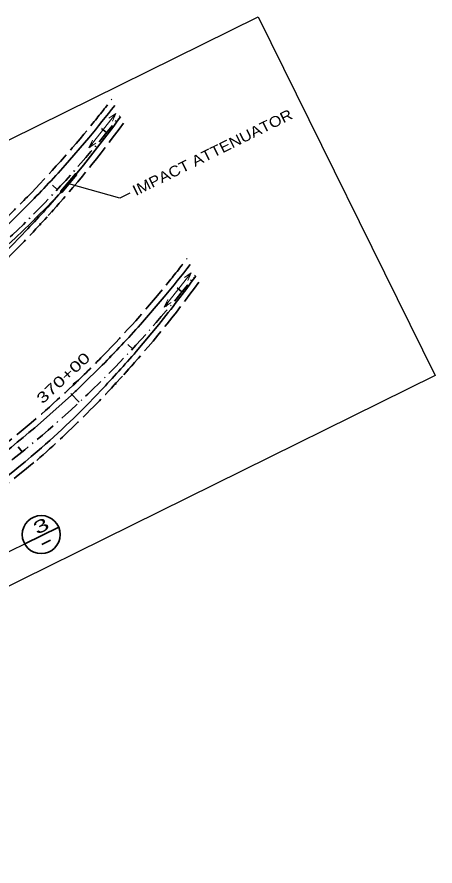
# Model space of a CAD drawing. Extents: x 2356431 to 2371438, y 6972864 to 6982525.
# Drawn here: x 2362282 to 2362836, y 6978847 to 6979972 of the extents above; entities that cross this region are included whole.
import ezdxf
from ezdxf.enums import TextEntityAlignment as Align

# ---------------------------------------------------------------- set-up
doc = ezdxf.new("R2010")
doc.units = 0
doc.header["$LTSCALE"] = 5.6
doc.linetypes.add('DOT_DASHED', pattern=[7.7, 5, -1.2, 0.3, -1.2])
doc.linetypes.add('LONG_DASHED', pattern=[7.5, 6, -1.5])
for name, color, linetype, lineweight in [('14', 7, 'Continuous', 13), ('17', 7, 'Continuous', 35), ('2', 7, 'Continuous', 35), ('24', 7, 'Continuous', 13), ('28', 7, 'Continuous', 35), ('6', 7, 'DOT_DASHED', 35), ('8', 7, 'Continuous', 13)]:
    doc.layers.add(name, color=color, linetype=linetype, lineweight=lineweight)

msp = doc.modelspace()

# ---------------------------------------------------------------- linework, layer by layer
at = {"layer": '14'}
for p, q in [((2362413.315, 6979843.481), (2362404.062, 6979837.394)), ((2362413.315, 6979843.481), (2362408.657, 6979833.432)), ((2362377.511, 6979798.212), (2362382.219, 6979808.24)), ((2362513.151, 6979632.555), (2362503.898, 6979626.468)), ((2362513.151, 6979632.555), (2362508.493, 6979622.506)), ((2362477.347, 6979587.286), (2362482.055, 6979597.314))]:
    msp.add_line(p, q, dxfattribs=at)
for points in [[(2362413.315, 6979843.481), (2362377.511, 6979798.212), (2362386.795, 6979804.255)], [(2362513.151, 6979632.555), (2362477.347, 6979587.286), (2362486.631, 6979593.329)]]:
    msp.add_lwpolyline(points, dxfattribs=at)
at = {"layer": '17', "lineweight": 13}
for centre in [(2362381.177, 6979803.33), (2362312.936, 6979696.769), (2362481.013, 6979592.404), (2362412.772, 6979485.843)]:
    msp.add_circle(centre, 1, dxfattribs=at)
at = {"layer": '2'}
for p, q in [((2362377.323, 6979811.601), (2362345.907, 6979775.127)), ((2362340.219, 6979739.244), (2362370.285, 6979775.188)), ((2362295.276, 6979721.222), (2362267.688, 6979694.092)), ((2362477.159, 6979600.675), (2362445.743, 6979564.201)), ((2362440.055, 6979528.318), (2362470.121, 6979564.262)), ((2362395.112, 6979510.296), (2362367.524, 6979483.166)), ((2362354.349, 6979470.72), (2362313.384, 6979433.972)), ((2362292.462, 6979273.717), (2362337.516, 6979295.812)), ((2362315.084, 6979272.776), (2362326.522, 6979278.422))]:
    msp.add_line(p, q, dxfattribs=at)
at = {"layer": '2', "lineweight": 25}
msp.add_line((2361792.105, 6979026.773), (2362292.462, 6979273.717), dxfattribs=at)
msp.add_lwpolyline([(2361285.115, 6979321.851), (2362601.555, 6979971.558), (2362836.023, 6979496.478), (2361519.583, 6978846.77)], close=True, dxfattribs=at)
at = {"layer": '2'}
msp.add_lwpolyline([(2362339.613, 6979738.775), (2362340.156, 6979740.907), (2362359.585, 6979763.851), (2362361.205, 6979762.514), (2362341.898, 6979739.544)], close=True, dxfattribs=at)
at = {"layer": '2', "lineweight": 25}
msp.add_lwpolyline([(2362431.818, 6979738.252), (2362418.363, 6979731.611), (2362350.947, 6979750.54)], dxfattribs=at)
at = {"layer": '2'}
msp.add_circle((2362314.274, 6979285.825), 25.166, dxfattribs=at)
at = {"layer": '2', "linetype": 'LONG_DASHED'}
for centre, radius, start, end in [((2361287.072, 6980718.904), 1410.395, 320.86316, 322.61144), ((2361287.072, 6980718.904), 1410.395, 315.67541, 320.86316), ((2361256.679, 6980676.098), 1440.395, 317.79711, 324.08069), ((2361287.072, 6980718.904), 1410.395, 313.40549, 315.67541), ((2361256.679, 6980676.098), 1440.395, 311.35741, 318.66625), ((2361386.908, 6980507.978), 1410.395, 320.86316, 322.61144), ((2361386.908, 6980507.978), 1410.395, 315.67541, 320.86316), ((2361356.514, 6980465.172), 1440.395, 317.79711, 324.08069), ((2361356.514, 6980465.172), 1440.395, 311.35741, 318.66625), ((2361386.908, 6980507.978), 1410.395, 313.40549, 315.67541), ((2361386.908, 6980507.978), 1410.395, 304.27695, 313.40549), ((2361361.776, 6980498.253), 1461.395, 297.31887, 310.34554)]:
    msp.add_arc(centre, radius, start, end, dxfattribs=at)
at = {"layer": '2'}
for centre, radius, start, end in [((2361287.072, 6980718.904), 1418.395, 320.23288, 322.45152), ((2361256.679, 6980676.098), 1432.395, 321.02703, 324.24964), ((2361287.072, 6980718.904), 1418.395, 315.3005, 318.28822), ((2361256.679, 6980676.098), 1432.395, 316.36601, 319.15253), ((2361540.868, 6980387.624), 1027.726, 310.56789, 317.07313), ((2361386.908, 6980507.978), 1418.395, 320.23288, 322.45152), ((2361356.514, 6980465.172), 1432.395, 321.02703, 324.24964), ((2361386.908, 6980507.978), 1418.395, 315.3005, 318.28822), ((2361356.514, 6980465.172), 1432.395, 316.36601, 319.15253), ((2361386.908, 6980507.978), 1418.395, 313.00532, 313.73747), ((2361640.703, 6980176.698), 1027.726, 310.56789, 317.07313), ((2361386.908, 6980507.978), 1418.395, 304.27695, 310.78219), ((2361361.776, 6980498.253), 1453.395, 297.31887, 310.6767)]:
    msp.add_arc(centre, radius, start, end, dxfattribs=at)
at = {"layer": '24'}
for p, q in [((2362416.001, 6979835.063), (2362412.956, 6979832.475)), ((2362382.155, 6979801.83), (2362379.322, 6979799.003)), ((2362515.837, 6979624.137), (2362512.792, 6979621.549)), ((2362481.991, 6979590.904), (2362479.158, 6979588.077)), ((2362363.091, 6979490.308), (2362356.576, 6979485.655))]:
    msp.add_line(p, q, dxfattribs=at)
for points in [[(2362311.277, 6979737.172), (2362308.112, 6979734.552), (2362305.084, 6979732.103)], [(2362411.113, 6979526.246), (2362407.948, 6979523.626), (2362404.92, 6979521.177)]]:
    msp.add_lwpolyline(points, dxfattribs=at)
at = {"layer": '28'}
for p, q in [((2362400.953, 6979818.333), (2362394.344, 6979823.677)), ((2362335.419, 6979742.827), (2362329.198, 6979748.619)), ((2362500.789, 6979607.407), (2362494.18, 6979612.751)), ((2362435.255, 6979531.901), (2362429.034, 6979537.693)), ((2362364.614, 6979461.15), (2362353.693, 6979472.843)), ((2362289.209, 6979395.499), (2362283.855, 6979402.1))]:
    msp.add_line(p, q, dxfattribs=at)
at = {"layer": '6'}
for centre in [(2361287.074, 6980718.905), (2361386.91, 6980507.979)]:
    msp.add_arc(centre, 1432.395, 296.26348, 322.17641, dxfattribs=at)
at = {"layer": '6', "linetype": 'Continuous'}
msp.add_arc((2361291.383, 6980720.837), 1436.395, 298.99553, 316.8666, dxfattribs=at)
at = {"layer": '8'}
for p, q in [((2362419.191, 6979839.168), (2362416.03, 6979836.274)), ((2362519.027, 6979628.242), (2362515.866, 6979625.348))]:
    msp.add_line(p, q, dxfattribs=at)

# ---------------------------------------------------------------- texts
at = {"layer": '2'}
for s, height, width, p in [('IMPACT ATTENUATOR', 14, 1.15, (2362439.694, 6979734.259)), ('3', 16.8, 1.6, (2362308.728, 6979285.416))]:
    msp.add_text(s, height=height, rotation=26.268, dxfattribs=dict(at, width=width)).set_placement(p)
at = {"layer": '28', "width": 1.4}
msp.add_text('370+00', height=14, rotation=43.044, dxfattribs=at).set_placement((2362348.232, 6979488.268), align=Align.CENTER)

doc.saveas('drawing.dxf')
